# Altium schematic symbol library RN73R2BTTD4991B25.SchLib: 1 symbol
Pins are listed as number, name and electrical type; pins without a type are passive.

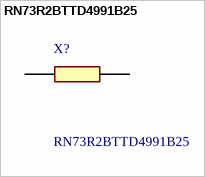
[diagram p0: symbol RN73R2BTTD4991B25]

## RN73R2BTTD4991B25
designator X?
Thin Film Resistors - SMD 4990 ohm 0.1% 0.25W; Manufacturer_Name: KOA Speer; Geometry.Height: 0.7mm
footprint RESC3216X70N
pins: 1, 2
